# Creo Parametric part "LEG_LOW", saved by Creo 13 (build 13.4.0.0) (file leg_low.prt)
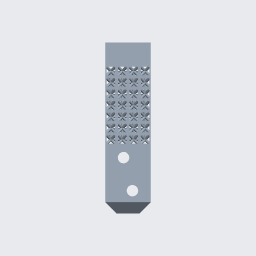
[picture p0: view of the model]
Units: millimeter Newton Second (mmNs); MM, TONNE, SECS
Materials in the file: PLA

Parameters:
  PTC_MATERIAL_NAME = "PLA"
  GRANTA_DATALINK_VERSION = "5"
  GRANTA_DATABASE_KEY = "Granta_Typical_Materials"
  GRANTA_IDENTITY_GUID = "b9b893b2-6906-4609-ab08-d879fcb43028"
  GRANTA_VERSION_GUID = "46d219ad-0776-45d4-90e4-94de701ee33b"
  GRANTA_MODEL_REFERENCE = "00000000-0000-0000-0000-000000000000"

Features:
  1. datum plane "RIGHT"
  2. datum plane "TOP"
  3. datum plane "FRONT"
  4. coordinate system
  5. protrusion
  6. protrusion
  7. protrusion

Other named items: LATTICE_1

Surfaces: 3429 cylinder, 23 plane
